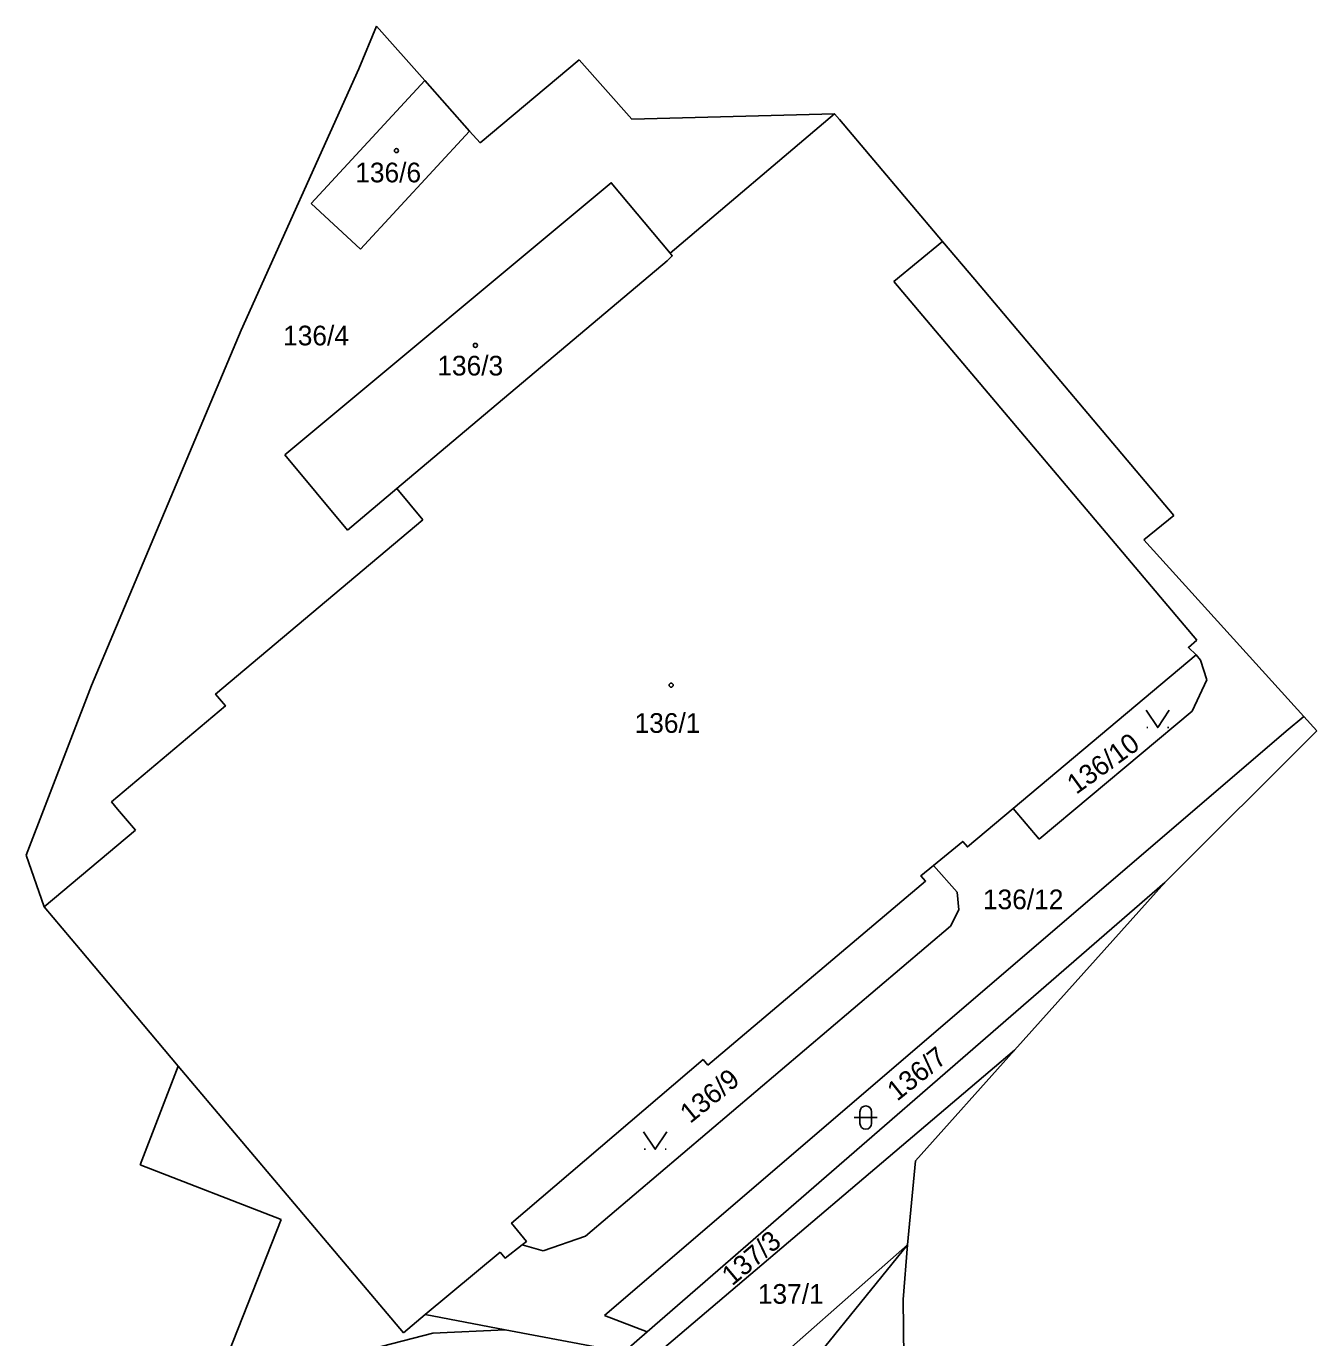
# Model space of a CAD drawing. Extents: x -670359 to -668019, y -978807 to -976674.
# Drawn here: x -670021.4 to -669909.9, y -977121.4 to -977008.1 of the extents above; entities that cross this region are included whole.
import ezdxf

# ---------------------------------------------------------------- set-up
doc = ezdxf.new("R2010")
doc.units = 0
for name, color, linetype in [('Hranice kat_území', 7, 'Continuous'), ('Hranice parcel', 7, 'Continuous'), ('Parcelní čísla', 7, 'Continuous'), ('Značky budov', 7, 'Continuous'), ('Značky kultur', 7, 'Continuous')]:
    doc.layers.add(name, color=color, linetype=linetype)

msp = doc.modelspace()

# ---------------------------------------------------------------- linework, layer by layer
at = {"layer": 'Hranice kat_území'}
for points in [[(-669992.62, -977011.79), (-669991.11, -977008.11)], [(-669991.11, -977008.11), (-669986.94, -977012.79)], [(-670002.78, -977034.35), (-669992.62, -977011.79)], [(-669982.16, -977018.18), (-669973.59, -977011)], [(-669973.59, -977011), (-669969.06, -977016.14)], [(-669986.94, -977012.79), (-669983.07, -977017.16)], [(-669969.06, -977016.14), (-669951.54, -977015.68)], [(-669951.54, -977015.68), (-669951.12, -977016.16)], [(-669942.2, -977026.71), (-669951.12, -977016.16)], [(-669983.07, -977017.16), (-669982.16, -977018.18)], [(-669942.2, -977026.71), (-669939.42, -977029.99)], [(-669939.42, -977029.99), (-669922.23, -977050.36)], [(-670015.73, -977065.05), (-670002.78, -977034.35)], [(-669922.23, -977050.36), (-669924.83, -977052.47)], [(-669924.83, -977052.47), (-669910.99, -977067.73)], [(-670015.73, -977065.05), (-670021.36, -977079.69)], [(-669910.99, -977067.73), (-669909.88, -977068.95)], [(-669909.88, -977068.95), (-669923, -977082.05)], [(-670021.36, -977079.69), (-670019.82, -977084.16)], [(-669923, -977082.05), (-669935.98, -977096.52)], [(-670019.82, -977084.16), (-670016.71, -977087.84)], [(-670008.23, -977097.9), (-670016.71, -977087.84)], [(-669935.98, -977096.52), (-669944.55, -977106.08)], [(-670011.51, -977106.44), (-670008.23, -977097.9)], [(-669999.35, -977111.15), (-670011.51, -977106.44)], [(-669944.55, -977106.08), (-669945.23, -977113.35)], [(-670006.38, -977129.04), (-669999.35, -977111.15)], [(-669945.23, -977113.35), (-669945.6, -977118.07)], [(-669945.6, -977118.07), (-669945.45, -977130.61)]]:
    msp.add_lwpolyline(points, dxfattribs=at)
at = {"layer": 'Hranice parcel'}
for points in [[(-669996.75, -977023.43), (-669986.94, -977012.79)], [(-669951.54, -977015.68), (-669965.74, -977027.72)], [(-669992.49, -977027.36), (-669983.07, -977017.16)], [(-669965.74, -977027.72), (-669970.83, -977021.62), (-669999.01, -977045.11)], [(-669996.75, -977023.43), (-669992.49, -977027.36)], [(-669942.2, -977026.71), (-669946.42, -977030.15)], [(-669966, -977028.37), (-669989.36, -977048.04)], [(-669966, -977028.37), (-669965.55, -977027.95), (-669965.74, -977027.72)], [(-669920.25, -977061.14), (-669946.42, -977030.15)], [(-669993.62, -977051.63), (-669999.01, -977045.11)], [(-669989.36, -977048.04), (-669993.62, -977051.63)], [(-669989.36, -977048.04), (-669987.1, -977050.73)], [(-669987.1, -977050.73), (-670005, -977065.78), (-670004.16, -977066.8), (-670013.98, -977075.09), (-670013.48, -977075.72)], [(-669920.31, -977062.39), (-669920.97, -977061.75), (-669920.25, -977061.14)], [(-669936.1, -977075.65), (-669920.31, -977062.39)], [(-669919.91, -977062.86), (-669920.31, -977062.39)], [(-669919.38, -977064.56), (-669919.91, -977062.86)], [(-669920.65, -977067.27), (-669919.38, -977064.56)], [(-669933.87, -977078.32), (-669920.65, -977067.27)], [(-669910.99, -977067.73), (-669912.53, -977068.97)], [(-669912.53, -977068.97), (-669971.42, -977119.44)], [(-670013.48, -977075.72), (-670011.93, -977077.54)], [(-669942.99, -977080.58), (-669940.46, -977078.5), (-669940.06, -977078.98), (-669936.1, -977075.65)], [(-669936.1, -977075.65), (-669933.87, -977078.32)], [(-670011.93, -977077.54), (-670019.82, -977084.16)], [(-669962.47, -977097.83), (-669943.67, -977081.93), (-669944.07, -977081.47), (-669942.99, -977080.58)], [(-669942.99, -977080.58), (-669940.95, -977082.9)], [(-669923, -977082.05), (-669967.72, -977120.86)], [(-669940.95, -977082.9), (-669940.8, -977084.4)], [(-669940.8, -977084.4), (-669941.51, -977085.83)], [(-669941.51, -977085.83), (-669973.04, -977112.58)], [(-669967.58, -977123.35), (-669935.98, -977096.52)], [(-669978.52, -977113.33), (-669978.15, -977113.04), (-669979.44, -977111.46), (-669962.88, -977097.34)], [(-669962.88, -977097.34), (-669962.47, -977097.83)], [(-670008.23, -977097.9), (-669988.78, -977120.94)], [(-669973.04, -977112.58), (-669976.71, -977113.86)], [(-669980.42, -977113.98), (-669980, -977114.48), (-669978.52, -977113.33)], [(-669976.71, -977113.86), (-669978.52, -977113.33)], [(-669959.66, -977126.05), (-669945.23, -977113.35)], [(-669945.23, -977113.35), (-669956.43, -977127.16)], [(-669980.42, -977113.98), (-669986.9, -977119.37)], [(-669986.9, -977119.37), (-669988.78, -977120.94)], [(-669986.9, -977119.37), (-669979.99, -977120.67)], [(-669967.72, -977120.86), (-669971.42, -977119.44)], [(-669991.49, -977122.33), (-669986.23, -977120.98)], [(-669979.99, -977120.67), (-669986.23, -977120.98)], [(-669979.99, -977120.67), (-669969.73, -977122.61)], [(-669969.73, -977122.61), (-669967.72, -977120.86)]]:
    msp.add_lwpolyline(points, dxfattribs=at)
at = {"layer": 'Značky budov'}
for centre in [(-669989.38, -977018.85), (-669982.56, -977035.67), (-669965.65, -977065.01)]:
    msp.add_circle(centre, 0.175, dxfattribs=at)
at = {"layer": 'Značky kultur'}
for p, q in [((-669924.57, -977068.67), (-669924.47, -977068.67)), ((-669922.77, -977068.67), (-669922.67, -977068.67)), ((-669949.84, -977102.35), (-669947.84, -977102.35)), ((-669949.34, -977101.85), (-669949.34, -977102.85)), ((-669948.34, -977101.85), (-669948.34, -977102.85)), ((-669967.98, -977105.09), (-669967.88, -977105.09)), ((-669966.18, -977105.09), (-669966.08, -977105.09))]:
    msp.add_line(p, q, dxfattribs=at)
for points in [[(-669924.62, -977067.17), (-669923.62, -977068.67), (-669922.62, -977067.17)], [(-669968.03, -977103.59), (-669967.03, -977105.09), (-669966.03, -977103.59)]]:
    msp.add_lwpolyline(points, dxfattribs=at)
for centre in [(-669989.38, -977018.85), (-669982.56, -977035.67), (-669965.65, -977065.01)]:
    msp.add_circle(centre, 0.175, dxfattribs=at)
for centre, start, end in [((-669948.84, -977101.85), 0, 180), ((-669948.84, -977102.85), 180, 0)]:
    msp.add_arc(centre, 0.5, start, end, dxfattribs=at)

# ---------------------------------------------------------------- texts
at = {"layer": 'Parcelní čísla'}
for s, p in [('136/6', (-669992.94, -977021.59)), ('136/4', (-669999.17, -977035.67)), ('136/3', (-669985.85, -977038.27)), ('136/1', (-669968.81, -977069.13)), ('136/12', (-669938.72, -977084.36)), ('137/1', (-669958.16, -977118.43))]:
    msp.add_text(s, height=1.7, dxfattribs=at).set_placement(p)
for s, rotation, p in [('136/10', 36.0274, (-669930.66, -977074.49)), ('136/7', 38.6598, (-669946.13, -977100.99)), ('136/9', 39.1248, (-669964.01, -977102.92)), ('137/3', 39.9225, (-669960.38, -977116.94))]:
    msp.add_text(s, height=1.7, rotation=rotation, dxfattribs=at).set_placement(p)

doc.saveas('drawing.dxf')
